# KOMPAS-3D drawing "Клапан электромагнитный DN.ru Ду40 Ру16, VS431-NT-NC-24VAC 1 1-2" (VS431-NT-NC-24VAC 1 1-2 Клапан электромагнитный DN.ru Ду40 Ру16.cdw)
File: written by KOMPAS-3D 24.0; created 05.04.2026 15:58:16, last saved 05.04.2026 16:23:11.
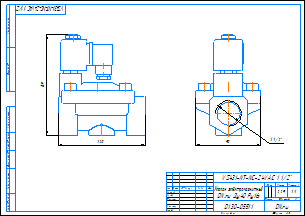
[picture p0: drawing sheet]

Document properties: c3d_UniqueCompID: ef56311e-7521-43dc-8291-0e6108b3d81d; Автор: artio; Класс точности: c; Знак неуказанной шероховатости: Шероховатость не задана; Рассекать на разрезах: Да; c3d_UniqueCompID: ef56311e-7521-43dc-8291-0e6108b3d81d; Автор: artio; Класс точности: c; Знак неуказанной шероховатости: Шероховатость не задана; Рассекать на разрезах: Да; c3d_UniqueCompID: ef56311e-7521-43dc-8291-0e6108b3d81d; Автор: artio; Класс точности: c; Знак неуказанной шероховатости: Шероховатость не задана; Рассекать на разрезах: Да; c3d_UniqueCompID: ef56311e-7521-43dc-8291-0e6108b3d81d; Автор: artio; Класс точности: c; Знак неуказанной шероховатости: Шероховатость не задана; Рассекать на разрезах: Да; Автор: artio; Форматы листов документа: A3; Полное имя файла: VS431-NT-NC-24VAC 1 1-2 Клапан электромагнитный DN.ru Ду40 Ру16.m3d; Масса: 2.285; Наименование: Клапан электромагнитный DN.ru Ду40 Ру16; Количество листов документа: 1; Примечание: D130-05511

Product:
- Body: Тело 1  | qty 1
    Масса: 3.859459
- Part/product: Клапан электромагнитный DN.ru Ду40 Ру16  | designation VS431-NT-NC-24VAC 1 1-2
    Масса: 2.285
    Раздел спецификации: Прочие изделия
    Примечание: D130-05511
    additional columns: ef56311e-7521-43dc-8291-0e6108b3d81d; artio; c; Шероховатость не задана; Да

Views: Вид 1, Спереди
Referenced files in C:\Users\artio\OneDrive\Рабочий стол\Клапан электромагнитный DN.ru\VS431\VS431-ET-NC\: VS431-ET-NC-24VAC 3-4 Клапан электромагнитный DN.ru Ду20 Ру16.m3d, VS431-ET-NC-24VAC 3-4 Клапан электромагнитный DN.ru Ду20 Ру16.cdw
Referenced files in C:\Users\artio\OneDrive\Рабочий стол\Клапан электромагнитный DN.ru\VS431\VS431-NT-NC\: VS431-NT-NC-24VAC 1 1-2 Клапан электромагнитный DN.ru Ду40 Ру16.m3d
Referenced files in C:\Users\artio\OneDrive\Рабочий стол\Клапан электромагнитный DN.ru\VS431\VS431-NT-NC\VS431-NT-NC-24VAC\Ду40\: VS431-NT-NC-24VAC 1 1-2 Клапан электромагнитный DN.ru Ду40 Ру16.m3d
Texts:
  VS431-NT-NC-24VAC 1 1-2
  Клапан электромагнитный
  DN.ru Ду40 Ру16
  VS431-NT-NC-24VAC 1 1/2"
  VS431-NT-NC-24VAC 1 1/2"-
  Клапан электромагнитный DN.ru Ду40 Ру16
  VS431-NT-NC-24VAC 1 1-2 Клапан электромагнитный DN.ru Ду40 Ру16
Dimensions and other numbers on the sheet: 0; 3; 2; 4; 90; 1 1/2"; 1:1; 1; 2,29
